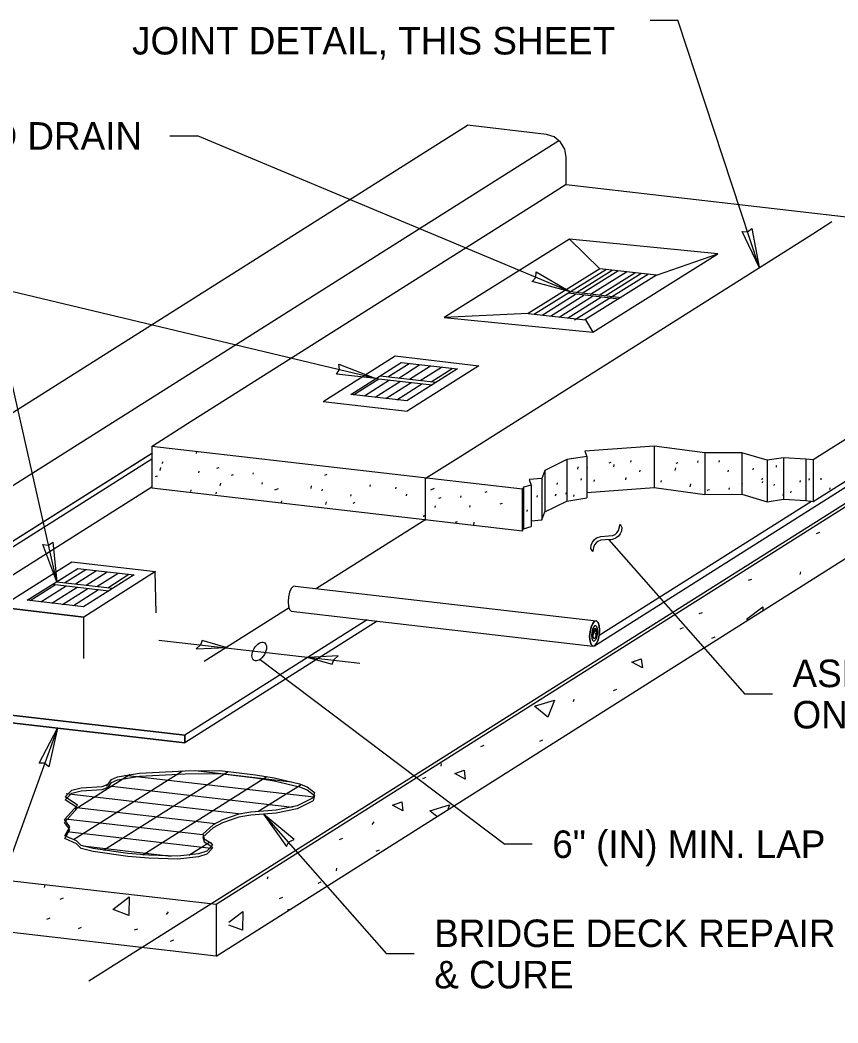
# Model space of a CAD drawing. Extents: x 99862 to 103151, y 100000 to 105076.
# Drawn here: x 102274 to 102749, y 103885 to 104468 of the extents above; entities that cross this region are included whole.
import ezdxf

# ---------------------------------------------------------------- set-up
doc = ezdxf.new("R2010")
doc.units = 0
for name, color, linetype in [('Level 1', 7, 'Continuous'), ('Level 10', 7, 'Continuous'), ('Level 15', 7, 'Continuous'), ('Level 2', 7, 'Continuous'), ('Level 20', 7, 'Continuous'), ('Level 3', 7, 'Continuous'), ('Level 4', 7, 'Continuous'), ('Level 5', 7, 'Continuous')]:
    doc.layers.add(name, color=color, linetype=linetype)

msp = doc.modelspace()

# ---------------------------------------------------------------- linework, layer by layer
at = {"layer": 'Level 1'}
for p, q in [((102487.4, 104260.72), (102499.69, 104268.49)), ((102493.66, 104259.99), (102505.95, 104267.76)), ((102527.8, 104265.28), (102498.45, 104246.73)), ((102540.25, 104267.17), (102498.53, 104240.8)), ((102499.93, 104259.27), (102512.22, 104267.04)), ((102506.19, 104258.55), (102518.48, 104266.31)), ((102512.46, 104257.82), (102524.75, 104265.59)), ((102467.45, 104250.31), (102482.12, 104259.59)), ((102473.71, 104249.59), (102488.39, 104258.86)), ((102479.98, 104248.86), (102494.65, 104258.14)), ((102486.24, 104248.14), (102500.92, 104257.42)), ((102492.51, 104247.42), (102507.18, 104256.69)), ((102299.58, 104141.09), (102311.87, 104148.85)), ((102305.85, 104140.36), (102318.13, 104148.13)), ((102352.43, 104147.54), (102310.72, 104121.17)), ((102312.11, 104139.64), (102324.4, 104147.41)), ((102318.38, 104138.92), (102330.67, 104146.68)), ((102352.72, 104123.53), (102352.17, 104147.53)), ((102339.98, 104145.65), (102310.63, 104127.1)), ((102324.64, 104138.19), (102336.93, 104145.96)), ((102279.63, 104130.68), (102294.3, 104139.96)), ((102285.9, 104129.96), (102300.57, 104139.23)), ((102292.16, 104129.23), (102306.84, 104138.51)), ((102298.43, 104128.51), (102313.1, 104137.79)), ((102304.69, 104127.78), (102319.37, 104137.06))]:
    msp.add_line(p, q, dxfattribs=at)
for points in [[(102590.96, 104372.37), (102575.4, 104362.54), (102371.05, 104233.36), (102350.98, 104220.68), (102350.82, 104220.58), (102350.6, 104220.44), (102350.42, 104220.33), (102350.28, 104220.23), (102350.24, 104220.21), (102350.24, 104196.16)], [(102449.84, 104246.43), (102491.55, 104272.8), (102540.25, 104267.17)], [(102465.77, 104250.5), (102495.12, 104269.06), (102527.8, 104265.28)], [(102480.44, 104259.78), (102513.13, 104256.01)], [(102482.83, 104261.29), (102515.51, 104257.51)], [(102449.84, 104246.43), (102498.53, 104240.8)], [(102498.45, 104246.73), (102465.77, 104250.5)], [(102481.21, 104118.78), (102369.43, 104048.12), (102169.65, 104071.2), (102167.45, 104071.91), (102165.59, 104073.42), (102164.35, 104075.52), (102163.91, 104077.87), (102163.91, 104098.53), (102350.74, 104216.63)], [(102163.91, 104077.87), (102163.91, 104080.79), (102163.91, 104098.53), (102350.24, 104216.31)], [(102350.24, 104212.81), (102168.59, 104097.99), (102168.59, 104081.69)], [(102350.24, 104196.51), (102168.59, 104081.69), (102169.03, 104079.34), (102170.27, 104077.24), (102172.13, 104075.73), (102174.33, 104075.02), (102369.43, 104052.48)], [(102350.24, 104196.51), (102350.31, 104196.15), (102350.31, 104196.15)], [(102262.02, 104126.8), (102303.73, 104153.17), (102352.43, 104147.54)], [(102277.95, 104130.87), (102307.3, 104149.43), (102339.98, 104145.65)], [(102295.01, 104141.66), (102327.7, 104137.88)], [(102292.63, 104140.15), (102325.31, 104136.37)], [(102310.63, 104127.1), (102277.95, 104130.87)], [(102262.02, 104126.8), (102310.72, 104121.17)], [(102310.72, 104097.12), (102310.72, 104121.17), (102262.02, 104126.8)], [(102475.42, 104119.47), (102369.43, 104052.48), (102369.43, 104048.12)], [(102163.91, 104098.53), (102163.91, 104077.87), (102163.91, 104077.87), (102165.59, 104073.42), (102169.65, 104071.2), (102169.65, 104071.2), (102369.43, 104048.12), (102369.43, 104048.12), (102369.43, 104052.48), (102369.43, 104052.48), (102174.33, 104075.02), (102174.33, 104075.02), (102170.27, 104077.24), (102168.59, 104081.69), (102168.59, 104081.69), (102168.59, 104097.99), (102168.59, 104097.99), (102163.91, 104098.53)]]:
    msp.add_lwpolyline(points, dxfattribs=at)
at = {"layer": 'Level 10'}
msp.add_line((102313.67, 103909.73), (102977.08, 104328.7), dxfattribs=at)
at = {"layer": 'Level 15'}
for p, q in [((102639.7, 104467.95), (102655.7, 104467.95)), ((102703.09, 104324.31), (102655.7, 104467.95)), ((102360.76, 104400.66), (102376.76, 104400.66)), ((102593.42, 104310.07), (102376.76, 104400.66)), ((102295.01, 104141.66), (102256.3, 104313.14)), ((102480.44, 104259.78), (102256.3, 104313.14)), ((102619.34, 104169.14), (102620.42, 104170.06)), ((102620.42, 104170.06), (102621.29, 104171.46)), ((102621.29, 104171.46), (102622.27, 104175.02)), ((102622.33, 104169.42), (102621.37, 104168.11)), ((102622.28, 104175.02), (102623.33, 104173.19)), ((102622.97, 104171.07), (102622.33, 104169.42)), ((102623.33, 104173.19), (102622.97, 104171.07)), ((102605.51, 104162.99), (102606.15, 104164.66)), ((102606.15, 104164.66), (102607.16, 104166.03)), ((102607.16, 104166.03), (102608.56, 104167.11)), ((102608.26, 104164.27), (102607.45, 104163.18)), ((102609.31, 104165.09), (102608.26, 104164.27)), ((102608.56, 104167.11), (102611.12, 104168.03)), ((102611.12, 104165.73), (102609.31, 104165.09)), ((102611.12, 104168.03), (102615.52, 104168.41)), ((102613.66, 104165.95), (102611.12, 104165.73)), ((102617.75, 104166.22), (102613.66, 104165.95)), ((102615.52, 104168.41), (102617.93, 104168.61)), ((102615.7, 104166.08), (102694.72, 104076.42)), ((102620.04, 104167.11), (102617.75, 104166.22)), ((102617.93, 104168.61), (102619.34, 104169.14)), ((102621.37, 104168.11), (102620.04, 104167.11)), ((102605.26, 104161.02), (102605.51, 104162.99)), ((102606.32, 104159.18), (102605.26, 104161.02)), ((102606.83, 104161.55), (102606.32, 104159.19)), ((102607.45, 104163.18), (102606.83, 104161.55)), ((102429.99, 104126.45), (102380.73, 104095.31)), ((102413.16, 104096.53), (102555.2, 103989.18)), ((102710.72, 104076.42), (102694.72, 104076.42)), ((102295.41, 104056.68), (102233.41, 103885.35)), ((102415.19, 104006.64), (102486.61, 103925.43)), ((102571.2, 103989.18), (102555.2, 103989.18)), ((102502.61, 103925.43), (102486.61, 103925.43))]:
    msp.add_line(p, q, dxfattribs=at)
for points in [[(102703.09, 104324.31), (102693.13, 104345.07), (102696.3, 104345), (102698.8, 104346.94)], [(102593.42, 104310.07), (102571.21, 104316.12), (102573.33, 104318.47), (102573.51, 104321.63)], [(102480.44, 104259.78), (102457.55, 104262.2), (102459.27, 104264.86), (102458.94, 104268.01)], [(102295.01, 104141.66), (102287.03, 104163.26), (102290.18, 104162.89), (102292.85, 104164.58)], [(102393.39, 104103.37), (102379.58, 104107.58), (102378.48, 104105.02), (102375.93, 104102.61)], [(102441.13, 104097.72), (102454.99, 104093.68), (102456.06, 104096.25), (102458.58, 104098.69)], [(102295.41, 104056.68), (102290.46, 104034.19), (102288.02, 104036.2), (102284.85, 104036.22)], [(102415.19, 104006.64), (102428.46, 103987.82), (102429.94, 103990.62), (102432.85, 103991.86)]]:
    msp.add_lwpolyline(points, close=True, dxfattribs=at)
msp.add_ellipse((102412.63, 104101.09), major_axis=(3, 5.2), ratio=0.57735, dxfattribs=at)
at = {"layer": 'Level 2'}
msp.add_lwpolyline([(102354.28, 104107.8), (102471.04, 104094.37)], dxfattribs=at)
at = {"layer": 'Level 3'}
for p, q in [((101986.04, 104060.75), (102533.58, 104406.86)), ((102579.49, 104401.56), (102533.58, 104406.86)), ((102037.31, 104050.75), (102586.57, 104397.94)), ((102583.88, 104400.14), (102579.49, 104401.56)), ((102587.6, 104397.1), (102583.88, 104400.14)), ((102590.09, 104392.92), (102587.6, 104397.1)), ((102590.96, 104388.22), (102590.09, 104392.92)), ((102590.96, 104372.37), (102590.96, 104388.22)), ((102376.29, 104217.16), (102376.1, 104216.21)), ((102356.55, 104211.33), (102356.36, 104210.37)), ((102615.88, 104210.69), (102617.12, 104211.17)), ((102628.56, 104212.13), (102628.37, 104211.18)), ((102654.8, 104210.45), (102656.04, 104210.93)), ((102667.48, 104211.89), (102667.29, 104210.94)), ((102679.8, 104212.1), (102679.61, 104211.14)), ((102355.22, 104207.96), (102354.9, 104206.37)), ((102377.51, 104205.95), (102377.32, 104205)), ((102388.06, 104207.62), (102389.3, 104208.1)), ((102409.14, 104205.01), (102408.94, 104204.06)), ((102597.79, 104208.33), (102597.54, 104207.06)), ((102602.92, 104208.21), (102603.42, 104208.4)), ((102618.67, 104209.68), (102618.42, 104208.41)), ((102633.76, 104206.49), (102633.57, 104205.54)), ((102654.36, 104207.86), (102654.05, 104206.27)), ((102685.01, 104206.46), (102684.82, 104205.5)), ((102699.55, 104207.54), (102699.36, 104206.59)), ((102712.98, 104209.12), (102712.79, 104208.16)), ((102352.36, 104202.76), (102353.59, 104203.24)), ((102390.15, 104199), (102389.84, 104197.41)), ((102396.46, 104203.57), (102397.7, 104204.05)), ((102414.34, 104199.37), (102414.15, 104198.42)), ((102450.79, 104203.64), (102452.03, 104204.11)), ((102585.76, 104199.1), (102585.57, 104198.15)), ((102599.55, 104201.56), (102599.36, 104200.6)), ((102607.15, 104200.79), (102606.96, 104199.84)), ((102625.61, 104202.16), (102625.36, 104200.89)), ((102646.08, 104200.55), (102645.89, 104199.59)), ((102692.95, 104198.81), (102693.46, 104199)), ((102704.76, 104201.9), (102704.57, 104200.95)), ((102704.9, 104199.97), (102704.71, 104199.02)), ((102726.8, 104200.39), (102726.61, 104199.44)), ((102732.12, 104201.67), (102731.93, 104200.72)), ((102738.92, 104201.88), (102738.73, 104200.93)), ((102372.91, 104195), (102372.72, 104194.05)), ((102387.73, 104193.67), (102387.54, 104192.72)), ((102421.73, 104195.03), (102423.8, 104195.82)), ((102442.86, 104197.43), (102442.54, 104195.84)), ((102449.14, 104195.48), (102448.95, 104194.53)), ((102477.13, 104197.92), (102476.94, 104196.97)), ((102491.96, 104196.59), (102491.77, 104195.64)), ((102512.28, 104195.14), (102514.35, 104195.93)), ((102543.85, 104193.63), (102545.08, 104194.11)), ((102590.96, 104193.46), (102590.77, 104192.51)), ((102663.04, 104198.45), (102662.72, 104196.87)), ((102672.9, 104194.8), (102674.14, 104195.27)), ((102685.58, 104196.24), (102685.39, 104195.28)), ((102711.71, 104198.42), (102711.52, 104197.47)), ((102716.91, 104192.78), (102716.72, 104191.83)), ((102721.48, 104194.22), (102721.29, 104193.27)), ((102744.13, 104196.24), (102743.94, 104195.29)), ((102425.49, 104188.68), (102425.3, 104187.73)), ((102451.53, 104188.03), (102451.22, 104186.44)), ((102465.85, 104192.27), (102465.65, 104191.32)), ((102467.15, 104187.31), (102468.38, 104187.79)), ((102498.09, 104192.55), (102497.9, 104191.6)), ((102517.04, 104190.17), (102518.28, 104190.64)), ((102529.72, 104191.61), (102529.52, 104190.65)), ((102552.63, 104186.85), (102553.87, 104187.32)), ((102574.03, 104191.71), (102573.84, 104190.75)), ((102584.82, 104192.58), (102584.56, 104191.31)), ((102595.3, 104192.19), (102595.11, 104191.24)), ((102514.81, 104185.76), (102514.62, 104184.81)), ((102534.92, 104185.97), (102534.73, 104185.01)), ((102568.2, 104183.44), (102568.01, 104182.49)), ((102508.31, 104180.27), (102508.12, 104179.31)), ((102526.58, 104176.22), (102527.81, 104176.69)), ((102537.38, 104176.2), (102537.06, 104174.61)), ((102736.38, 104169.66), (102738.29, 104170.39)), ((102727, 104147.34), (102726.7, 104145.87)), ((102696.87, 104142.48), (102698.79, 104143.22)), ((102668.22, 104123.12), (102670.13, 104123.85)), ((102696.57, 104119.49), (102695.79, 104119.77)), ((102657.22, 104114.3), (102659.13, 104115.03)), ((102675.57, 104108.84), (102677.48, 104109.58)), ((102618.43, 104078.45), (102620.34, 104079.18)), ((102595.28, 104073.26), (102594.98, 104071.8)), ((102575.55, 104049.02), (102577.46, 104049.76)), ((102541.31, 104045.99), (102543.22, 104046.73)), ((102518.41, 104035.98), (102518.12, 104034.51)), ((102304.79, 103991.85), (102368, 104031.81)), ((102305.71, 104009.59), (102337.76, 104029.85)), ((102322.12, 103985.64), (102394.69, 104031.51)), ((102375.61, 104031.96), (102431.46, 104025.5)), ((102334.65, 104029.35), (102444.45, 104016.67)), ((102345.09, 103983), (102417, 104028.46)), ((102411.91, 104008.09), (102436.93, 104023.9)), ((102507.61, 104027.41), (102509.52, 104028.15)), ((102300.53, 104018.62), (102402.25, 104006.87)), ((102323.8, 104023.27), (102432.02, 104010.77)), ((102306.51, 104010.6), (102387.31, 104001.26)), ((102515.74, 104005.19), (102511.94, 104008.4)), ((102300, 104004.01), (102379.85, 103994.79)), ((102479.13, 104002.14), (102477.96, 104000.67)), ((102300.86, 103996.58), (102384.79, 103986.88)), ((102043.41, 103994.04), (102387.68, 103954.27)), ((102371.79, 103982.73), (102383.85, 103990.34)), ((102459.34, 103991.87), (102461.25, 103992.61)), ((102310.12, 103988.17), (102361.53, 103982.24)), ((102480.5, 103985.18), (102482.41, 103985.91)), ((102457.6, 103975.17), (102457.3, 103973.7)), ((102387.68, 103924.23), (101985.53, 103970.69)), ((102288.11, 103965.5), (102287.82, 103964.03)), ((102417.56, 103970.27), (102417.27, 103968.8)), ((102446.8, 103966.6), (102448.71, 103967.34)), ((102297.08, 103957.24), (102298.99, 103957.98)), ((102387.68, 103954.27), (102387.68, 103924.23)), ((102424.36, 103957.62), (102426.27, 103958.35)), ((102359.78, 103949.82), (102358.6, 103948.35)), ((102429.17, 103951.03), (102431.18, 103951.73)), ((102429.66, 103950.77), (102429.17, 103951.03)), ((102289.24, 103945.72), (102291.15, 103946.46)), ((102307.59, 103940.27), (102309.5, 103941)), ((102340.25, 103939.37), (102342.16, 103940.11)), ((102361.14, 103932.86), (102363.05, 103933.59))]:
    msp.add_line(p, q, dxfattribs=at)
for points in [[(102387.68, 103954.27), (102935.3, 104300.43)], [(102387.68, 103924.23), (102935.3, 104270.4)], [(102695.6, 104119.86), (102705.16, 104127.09), (102705.13, 104124.9)], [(102607.86, 104111.85), (102607.86, 104111.1), (102608.47, 104112.23), (102607.86, 104114.11), (102606.63, 104111.1)], [(102629.11, 104094.95), (102634.55, 104096.86), (102635.28, 104091.72), (102629.11, 104094.95)], [(102572.6, 104069.35), (102584.06, 104072.88), (102580.25, 104062.89), (102572.75, 104069.21)], [(102389.72, 104032.06), (102410.58, 104029.46), (102421.31, 104027.7), (102436.08, 104024.18), (102440.55, 104022.45), (102444.75, 104019.14), (102444.02, 104016.14), (102434.67, 104011.52), (102422.58, 104009.04), (102407.81, 104007.7), (102400.89, 104006.58), (102391.23, 104003.27), (102385.87, 104000.41), (102379.9, 103994.94), (102380.66, 103992.3), (102384.51, 103989.92), (102385.55, 103988.61), (102382.19, 103985.22), (102377.3, 103983.64), (102365.45, 103982.29), (102348.53, 103982.75), (102336.34, 103983.82), (102316.27, 103986.64), (102309.25, 103988.51), (102306.46, 103991.12), (102299.69, 103994.14), (102302.7, 103999.37), (102299.64, 104003.45), (102307.03, 104011.94), (102299.87, 104016.67), (102303.8, 104020.5), (102309.14, 104021.85), (102321.44, 104022.68), (102324.92, 104024.1), (102326.78, 104026.79), (102330.3, 104028.35), (102343.15, 104030.48), (102369.69, 104031.85), (102389.72, 104032.06)], [(102389.72, 104030.34), (102410.58, 104027.73), (102421.31, 104025.97), (102436.08, 104022.45), (102440.55, 104020.72), (102444.75, 104017.42), (102444.02, 104014.41), (102434.67, 104009.79), (102422.58, 104007.31), (102407.81, 104005.98), (102400.89, 104004.85), (102391.23, 104001.54), (102385.87, 103998.68), (102379.9, 103993.22), (102380.66, 103990.58), (102384.51, 103988.19), (102385.55, 103986.89), (102382.19, 103983.49), (102377.3, 103981.91), (102365.45, 103980.56), (102348.53, 103981.02), (102336.34, 103982.09), (102316.27, 103984.91), (102309.25, 103986.78), (102306.46, 103989.4), (102299.69, 103992.41), (102302.7, 103997.64), (102299.64, 104001.73), (102307.03, 104010.22), (102299.87, 104014.94), (102303.8, 104018.77), (102309.14, 104020.12), (102321.44, 104020.95), (102324.92, 104022.37), (102326.78, 104025.06), (102330.3, 104026.62), (102343.15, 104028.75), (102369.69, 104030.12), (102389.72, 104030.34)], [(102526.17, 104030.27), (102531.61, 104032.18), (102532.34, 104027.04), (102526.17, 104030.27)], [(102489.98, 104011.84), (102495.42, 104013.75), (102496.15, 104008.61), (102489.98, 104011.84)], [(102511.79, 104008.54), (102523.25, 104012.07), (102522.18, 104009.25)], [(102327.62, 103951.29), (102337.18, 103958.52), (102337.01, 103947.82), (102327.81, 103951.2)], [(102395.03, 103943.94), (102403.08, 103950.03), (102402.91, 103939.33), (102395.03, 103942.22)]]:
    msp.add_lwpolyline(points, dxfattribs=at)
at = {"layer": 'Level 4'}
for p, q in [((102590.96, 104372.37), (102926.21, 104333.65)), ((102592.83, 104340.68), (102520.14, 104295.21)), ((102592.83, 104340.68), (102610.54, 104323.49)), ((102679.1, 104332.17), (102592.83, 104340.68)), ((102926.21, 104333.65), (102734.39, 104212.39)), ((102606.41, 104286.7), (102679.1, 104332.17)), ((102610.54, 104323.49), (102568.83, 104297.5)), ((102614.27, 104323.07), (102572.57, 104297.08)), ((102596.92, 104309.65), (102617.68, 104322.63)), ((102600.21, 104309.29), (102620.96, 104322.27)), ((102605.14, 104308.72), (102625.9, 104321.7)), ((102610.08, 104308.15), (102630.83, 104321.13)), ((102643.41, 104319.74), (102610.54, 104323.49)), ((102595.83, 104293.71), (102638.75, 104320.47)), ((102643.41, 104319.74), (102601.7, 104293.75)), ((102613.62, 104307.74), (102634.37, 104320.73)), ((102621.53, 104305.79), (102592.04, 104309.2)), ((102622.92, 104306.66), (102593.42, 104310.07)), ((102734.39, 104188.34), (102926.21, 104309.59)), ((102576.89, 104296.57), (102596.3, 104308.71)), ((102581.83, 104296), (102601.23, 104308.14)), ((102586.77, 104295.43), (102606.17, 104307.57)), ((102591.7, 104294.86), (102611.11, 104307)), ((102568.83, 104297.5), (102520.14, 104295.21)), ((102520.14, 104295.21), (102606.41, 104286.7)), ((102568.83, 104297.5), (102602.14, 104293.71)), ((102602.14, 104293.71), (102606.41, 104286.7)), ((102642.07, 104220.44), (102601.7, 104217.43)), ((102734.39, 104212.39), (102734.39, 104188.34)), ((102576.69, 104201.62), (102569.41, 104201.1)), ((102566.19, 104196.54), (102565.47, 104195.35)), ((102602.92, 104193.47), (102642.07, 104196.38)), ((102642.07, 104196.38), (102671.43, 104192.43)), ((102671.43, 104192.43), (102692.95, 104192.46)), ((102692.95, 104192.46), (102707.61, 104188.15)), ((102707.61, 104188.15), (102717.17, 104189.66)), ((102717.17, 104189.66), (102730.21, 104188.84)), ((102730.21, 104188.84), (102734.39, 104188.34))]:
    msp.add_line(p, q, dxfattribs=at)
for points in [[(102745.28, 104350.71), (102745.28, 104350.71), (102734.1, 104343.65), (102529.75, 104214.47), (102509.68, 104201.79), (102509.52, 104201.69), (102509.3, 104201.55), (102509.12, 104201.44), (102508.98, 104201.34), (102508.94, 104201.32), (102508.94, 104177.27)], [(102643.41, 104319.74), (102679.1, 104332.17)], [(102565.47, 104171.29), (102565.47, 104195.35), (102350.24, 104220.21)], [(102601.7, 104217.43), (102602.92, 104214.37), (102602.92, 104190.31)], [(102671.43, 104216.49), (102642.07, 104220.44), (102642.07, 104196.38)], [(102692.95, 104216.52), (102671.43, 104216.49), (102671.43, 104192.43)], [(102707.61, 104212.21), (102692.95, 104216.52), (102692.95, 104192.46)], [(102591.25, 104212.6), (102578.52, 104206.32), (102578.52, 104182.27)], [(102602.92, 104214.37), (102591.25, 104212.6), (102591.25, 104188.54)], [(102717.17, 104213.72), (102707.61, 104212.21), (102707.61, 104188.15)], [(102730.21, 104212.9), (102717.17, 104213.72), (102717.17, 104189.66)], [(102734.39, 104212.39), (102730.21, 104212.9), (102730.21, 104188.84)], [(102578.52, 104206.32), (102576.69, 104201.62), (102576.69, 104177.57)], [(102569.41, 104201.1), (102570.58, 104197.77), (102570.58, 104173.71)], [(102350.24, 104196.16), (102565.47, 104171.29), (102566.19, 104172.48), (102570.58, 104173.71)], [(102570.58, 104197.77), (102566.19, 104196.54), (102566.19, 104172.48)], [(102570.58, 104177.13), (102576.69, 104177.57), (102578.52, 104182.27), (102591.25, 104188.54), (102602.92, 104190.31)]]:
    msp.add_lwpolyline(points, dxfattribs=at)
at = {"layer": 'Level 5'}
for p, q in [((102610.15, 104110.58), (102733.36, 104188.46)), ((102509.35, 104177.77), (102445.92, 104137.68)), ((102607.46, 104108.84), (102608.81, 104109.69)), ((102607.46, 104108.84), (102608.81, 104109.69))]:
    msp.add_line(p, q, dxfattribs=at)
for points in [[(102607.39, 104104.47), (102915.41, 104299.18), (102915.41, 104302.76)], [(102433.47, 104139.12), (102432.36, 104138.96), (102431.25, 104137.71), (102430.3, 104135.57), (102429.67, 104132.86), (102429.45, 104130), (102429.67, 104127.41), (102430.3, 104125.5), (102431.25, 104124.55), (102606.35, 104104.32), (102605.41, 104105.27), (102604.78, 104107.18), (102604.56, 104109.77), (102604.78, 104112.63), (102605.41, 104115.34), (102606.35, 104117.48), (102607.46, 104118.73), (102608.58, 104118.89)], [(102433.47, 104139.12), (102608.58, 104118.89), (102609.52, 104117.94), (102610.15, 104116.03), (102610.37, 104113.44), (102610.15, 104110.58), (102609.52, 104107.87), (102608.58, 104105.73), (102607.46, 104104.48), (102606.35, 104104.32)], [(102607.46, 104104.48), (102608.58, 104105.73), (102609.52, 104107.87), (102610.15, 104110.58), (102610.37, 104113.44), (102610.15, 104116.03), (102609.52, 104117.94), (102608.58, 104118.89), (102607.46, 104118.73), (102606.35, 104117.48), (102605.41, 104115.34), (102604.78, 104112.63), (102604.56, 104109.77), (102604.78, 104107.18), (102605.41, 104105.27), (102606.35, 104104.32), (102607.46, 104104.48)], [(102607.46, 104107.25), (102608.14, 104108.01), (102608.72, 104109.32), (102609.11, 104110.98), (102609.24, 104112.73), (102609.11, 104114.31), (102608.72, 104115.48), (102608.14, 104116.06), (102607.46, 104115.96), (102606.78, 104115.2), (102606.21, 104113.89), (102605.82, 104112.23), (102605.68, 104110.48), (102605.82, 104108.9), (102606.21, 104107.73), (102606.78, 104107.15), (102607.46, 104107.25)], [(102607.46, 104108.84), (102607.9, 104109.33), (102608.26, 104110.16), (102608.51, 104111.21), (102608.59, 104112.32), (102608.51, 104113.32), (102608.26, 104114.06), (102607.9, 104114.43), (102607.46, 104114.37), (102607.03, 104113.88), (102606.67, 104113.05), (102606.42, 104112), (102606.34, 104110.89), (102606.42, 104109.89), (102606.67, 104109.15), (102607.03, 104108.78), (102607.46, 104108.84)], [(102607.46, 104104.48), (102608.58, 104105.73), (102609.52, 104107.87), (102610.14, 104110.53)], [(102607.46, 104108.84), (102608.81, 104109.69)], [(102610.14, 104110.53), (102610.14, 104110.53)]]:
    msp.add_lwpolyline(points, dxfattribs=at)

# ---------------------------------------------------------------- texts
at = {"layer": 'Level 20'}
for s, p in [('JOINT DETAIL, THIS SHEET', (102338.83, 104447.95)), ('RECESSED DRAIN', (102154.36, 104392.66)), ('BRIDGE DECK REPAIR', (102514.29, 103929.43)), ('& CURE', (102514.29, 103905.43))]:
    msp.add_text(s, height=16, dxfattribs=at).set_placement(p)
for s, p in [('ASPHALT TACK COAT ', (102722.4, 104080.42)), ('ON MEMBRANE', (102722.4, 104056.42)), ('6" (IN) MIN. LAP', (102582.88, 103981.18))]:
    msp.add_text(s, height=16, rotation=360, dxfattribs=at).set_placement(p)

doc.saveas('drawing.dxf')
